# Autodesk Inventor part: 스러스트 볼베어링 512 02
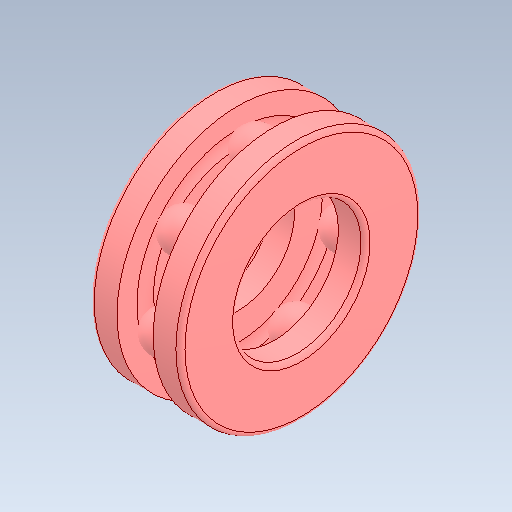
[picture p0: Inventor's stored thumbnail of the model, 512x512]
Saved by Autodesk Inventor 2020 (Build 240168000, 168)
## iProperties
Created: 2024-09
Part Number: 스러스트 볼베어링 512 02
Material: 강철, 연강
Description: 롤링 베어링 - 플랫 뒷면이 있는 스러스트 볼 베어링
Document SubType Name: Modeling
Designer: oem
Density: 7.85 g/cm^3
Appearance: 기본값
Author: jhkim
Sending System: Autodesk Inventor 2025
Preprocessor: ST-DEVELOPER v20
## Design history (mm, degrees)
feature "Solid1"
feature "Solid1:1"
feature "Solid1:2"
feature "Solid1:3"
feature "Solid1:4"
feature "Solid1:5"
feature "Solid1:6"
feature "Solid1:7"
feature "Solid1:8"
node "솔리드1"
node "솔리드2"
node "솔리드3"
node "솔리드4"
node "솔리드5"
node "솔리드6"
node "솔리드7"
node "솔리드8"
node "솔리드9"
